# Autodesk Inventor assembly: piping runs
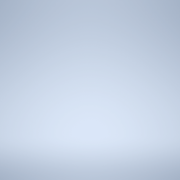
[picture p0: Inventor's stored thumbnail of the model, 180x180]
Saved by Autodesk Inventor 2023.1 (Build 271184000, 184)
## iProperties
Name: Hydraulic Hose - Male Taper Thread
ActiveState: False
PipeType: Flexible Hose
RoutePreview: Solid
Material: UnInitValue
Standard: UnInitValue
FittingMaterial: UnInitValue
FittingStandard: UnInitValue
RouteDirection90: UnInitValue
RouteDirection45: UnInitValue
DiameterType: Nominal
Diameter: 1/2
Schedule: ID=0.5
OD: 2.235200000000000e+000
ID: 1.270000000000000e+000
Ending: UnInitValue
IntermediateSegmentsMin: UnInitValue
IntermediateSegmentsMax: UnInitValue
IntermediateSegmentsInc: UnInitValue
TerminationSegmentsMin: UnInitValue
TerminationSegmentsMax: UnInitValue
TerminationSegmentsInc: UnInitValue
RoundUpValue: 0.125 in
SolidRoutePreviewColor: 12632064
PipingComponentColor: As Material
PipeKey: v3#d489867e-ac9b-47ea-b952-0a1b885f66be#4
CouplingKey: UnInitValue
Elbow90Key: UnInitValue
Elbow45Key: UnInitValue
_ComponentInfo: <CS><C N="Pipe" R="1.117600" OR="1.117600" IR="0.635000" PL="PL" PartType="" SymKey="" PN="Parker Hydraulic Hose - No Skive 1/2"><CO N="1"><FE V="0"/><FD V="0"/
BendRadius: 0.500 in
StartFittingKey: v3#c8250148-a7b6-458b-b7bd-3b56763ca7cc#13
EndFittingKey: v3#c8250148-a7b6-458b-b7bd-3b56763ca7cc#13
SuppressStartFitting: False
SuppressEndFitting: False
UseSubASM: True
DefaultBendRadius: UnInitValue
FlangeKey: UnInitValue
Gap: UnInitValue
GasketKey: UnInitValue
IsButtWelded: UnInitValue
IsFlanged: UnInitValue
MixedUnits: UnInitValue
ShowGap: UnInitValue
UseFlangsForCouplings: UnInitValue
BendRadius: UnInitValue
Diameter: 6
Elbow90Key: v3#97ecdcaf-8aa3-4fb0-8b6a-3da783de2ad5#108
EndFittingKey: UnInitValue
Gap: 0.062 inch
ID: UnInitValue
IntermediateSegmentsInc: 0.00001 in
IntermediateSegmentsMax: 200 inch
IntermediateSegmentsMin: 3 inch
IsButtWelded: True
IsFlanged: False
Name: ASTM A 53/A-ASME B16.9 - Steel Butt Welded Pipe
OD: UnInitValue
PipeKey: v3#4ce5e9fa-6da0-4801-ac02-ee7a0fb518d6#77
PipeType: Rigid Pipe
RoundUpValue: UnInitValue
RouteDirection45: False
RouteDirection90: True
Schedule: 40
ShowGap: True
StartFittingKey: UnInitValue
SuppressEndFitting: UnInitValue
SuppressStartFitting: UnInitValue
TerminationSegmentsInc: 0.00001 in
TerminationSegmentsMax: 200 inch
TerminationSegmentsMin: 3 inch
UseSubASM: UnInitValue
_ComponentInfo: <CS><C N="Elbow90" ER="15.240000" S1="15.240000" S2="15.240000" D1="0.000000" D2="0.000000" PartType="fitting" SymKey="ELBW"><CO N="1"><FE V="2"/><FD V="0"/><ET
MixedUnits: False
Name: JIS G 3458/JIS B 2316 -  Welded Steel Pipe and Fittings
RouteDirection45: True
Diameter: M40
Schedule: 80
IntermediateSegmentsMin: 60.000 mm
IntermediateSegmentsMax: 5000.000 mm
IntermediateSegmentsInc: 1.000 mm
TerminationSegmentsMin: 60.000 mm
TerminationSegmentsMax: 5000.000 mm
TerminationSegmentsInc: 1.000 mm
PipeKey: v3#da14b0ab-0b36-4851-8d66-8c9cd0bcbe86#23
CouplingKey: v3#12b64993-10e6-4915-8315-0c0cce209ad0#8
Elbow90Key: v3#1f65ece3-c41a-48d4-8661-909ed34ade86#8
Elbow45Key: v3#28e76e79-e22c-40ab-8be2-ff545b1407c5#8
_ComponentInfo: <CS><C N="Pipe" R="2.430000" IR="1.920000" PL="PL" PN="JIS G 3458 Pipe 40 A x Sch 80"><CO N="1"><FE V="0"/><FD V="1"/><ET V="Welded"/><NS  V="M40"/><MA V="0.000
CategoryName: UnInitValue
Name: Hydraulic Hose - Female Taper Thread
StartFittingKey: v3#cc3bd835-95a2-497d-9893-176cd9c426f6#7
EndFittingKey: v3#cc3bd835-95a2-497d-9893-176cd9c426f6#7
Name: Hydraulic Hose - SAE Flanged Connection
StartFittingKey: v3#933069c9-73b6-4141-af99-628d4a97b2c2#1
EndFittingKey: v3#933069c9-73b6-4141-af99-628d4a97b2c2#1
Name: ASTM A53/A53M-ASME B16.11 - Welded Steel Pipe
Material: Steel
Standard: ASTM A 53/A 53M
FittingMaterial: Steel
FittingStandard: ASME B16.11
OD: Undefined
ID: Undefined
IntermediateSegmentsMin: 1.000 in
IntermediateSegmentsMax: 200.000 in
IntermediateSegmentsInc: 0.100 in
TerminationSegmentsMin: 1.000 in
TerminationSegmentsMax: 200.000 in
TerminationSegmentsInc: 0.100 in
PipeKey: v3#4ce5e9fa-6da0-4801-ac02-ee7a0fb518d6#7
CouplingKey: v3#ed415c76-4cec-44a3-ba67-72e47bf70384#4
Elbow90Key: v3#82a08401-12d7-413b-b7f9-9cf3b607be7b#4
Elbow45Key: v3#2e5fd082-3851-4eb0-bde1-6c7078a7d72b#4
_ComponentInfo: <CS><C N="Pipe" R="1.066800" IR="0.789940" PL="PL" PN="ASTM A 53/A 53M Pipe 1/2 - Schedule 40"><CO N="1"><FE V="0"/><FD V="0"/><ET V="Welded"/><NS  V="1/2"/><MA
Elbow90Key: v3#6a678020-d9d9-4685-bba9-906b9a167083#10
FlangeKey: v3#c11442d2-c568-438f-a870-8ac9b5b636cb#10
GasketKey: v3#2a41914c-f5fb-4682-9c6a-1870d826d3d0#23
IntermediateSegmentsInc: 0.1 inch
IsButtWelded: False
IsFlanged: True
Name: ASTM A 53/A-ASME B16.5 - Flanged Steel Threaded Pipe
PipeKey: v3#c5bd7d28-cdb3-4507-9f3d-c2787d93fe8a#40
TerminationSegmentsInc: 0.1 inch
_ComponentInfo: <CS><C N="Elbow90" ER="21.590000" S1="21.590000" S2="21.590000" D1="0.000000" D2="0.000000" PartType="fitting" SymKey="ELFL"><CO N="1"><FE V="2"/><FD V="1"/><ET
ElbowCustomKey: UnInitValue
IsSelfDraining: False
Name: ISO 2531 - Flanged Ductile Iron Pipe and Fittings
Schedule: PN10
IntermediateSegmentsMin: 1000.000 mm
IntermediateSegmentsMax: 9000.000 mm
IntermediateSegmentsInc: 10.000 mm
TerminationSegmentsMin: 1000.000 mm
TerminationSegmentsMax: 9000.000 mm
TerminationSegmentsInc: 10.000 mm
PipeKey: v3#f52fbdcb-ece8-4303-8b76-5dbe8c7f2f9c#16
Elbow90Key: v3#451ae64e-c79d-4cba-b533-c09b8090ecb2#1
Elbow45Key: v3#81684a3f-f2a4-4fe6-95b1-f067ddead22f#1
_ComponentInfo: <CS><C N="Pipe" R="2.700000" IR="2.000000" PL="PL" PN="ISO 2531 Pipe with Integrally Cast Flanges DN40 PN 10"><CO N="1"><FE V="0"/><FD V="0"/><ET  V="Flanged"/>
Name: ASME B36.10M-ASME B16.11 - Steel Threaded Pipe
ActiveState: True
Material: Wrought Steel
Standard: ASME B36.10M
Schedule: 30
OD: 2.1336
ID: 1.651
IntermediateSegmentsMin: 2.000 in
TerminationSegmentsMin: 2.000 in
PipeKey: v3#4a736116-503a-44ad-a922-868ac6b46736#1
CouplingKey: v3#52ad3977-2b89-4007-a6a6-7626bac0ae85#4
Elbow90Key: v3#160eac10-3e6f-4b5c-839c-61eee0d373dc#4
Elbow45Key: v3#5c2ab816-abcb-49a6-a106-4733af000f51#4
_ComponentInfo: <CS><C N="Pipe" R="1.066800" IR="0.825500" PL="PL" PN="ASME B36.10M Pipe with Threaded Ends 1/2 - Schedule 30"><CO N="1"><FE V="0"/><FD V="1"/><ET  V="Threaded"
Angle: 92.00 deg
Diameter: 1
Elbow45Key: v3#bf26aa2a-f3dd-474c-8758-922a145c2b02#15
Elbow90Key: v3#3e93288f-9bb7-4e46-9d6b-544f8c20ca1c#3
ElbowCustomKey: v3#1f3bd44a-47ab-42f9-b3e0-74afa0c3f0ca#3
Gap: 0.094 in
IsSelfDraining: True
Name: ASME BPE - Butt Welded
PipeKey: v3#b10c956f-6fc6-429e-8056-0864a8581764#35
Schedule: ID=0.87
_ComponentInfo: <CS><C N="Pipe" R="1.270000" OR="1.270000" IR="1.104900" PL="PL" PartType="pipe" SymKey="" PN="ASTM A 269 Tube with Welded ends 1 x 0.87"><CO N="1"><FE V="2"/><
Name: DIN 2458/DIN 2605 - Welded Steel Pipe and Fittings
Schedule: ID=30.7
PipeKey: v3#dcef2839-8903-4c98-a96c-b861f5d9bb7f#98
Elbow90Key: v3#ace818b0-7b7c-4ad9-b19c-6da358a202c1#17
Elbow45Key: v3#97879d80-057e-491b-840b-74a9b3a7cf63#17
_ComponentInfo: <CS><C N="Pipe" R="2.415000" IR="1.535000" PL="PL" PN="DIN 2458 Pipe 48.3 x 8.8"><CO N="1"><FE V="2"/><FD V="0"/><ET V="Welded"/><NS V="M40"/><MA  V="0.000000"/
Name: JIS G 3442/JIS B 2301 Threaded Steel Pipe and Iron Fittings
Schedule: ID=16.1
IntermediateSegmentsMin: 20.000 mm
TerminationSegmentsMin: 20.000 mm
PipeKey: v3#9964fba4-9d5a-4d75-85a8-e38022ccdce1#2
CouplingKey: v3#181262db-c004-4877-bc40-c64b931a44f6#3
Elbow90Key: v3#6c92b367-65e9-486b-b952-db434ae2548d#3
Elbow45Key: v3#960407aa-00b9-4d72-aae7-d50595845cfd#3
_ComponentInfo: <CS><C N="Pipe" R="1.085000" IR="0.805000" PL="PL" PN="JIS G 3442 Pipe with Threaded Ends 21.7 x 2.8"><CO N="1"><FE V="0"/><FD V="1"/><ET V="Threaded"/><NS V="1
Name: Hydraulic Hose - Female Thread - Swivel
StartFittingKey: v3#c5e461f5-5e73-4f2e-8c1e-4358d4d6f46c#4
EndFittingKey: v3#c5e461f5-5e73-4f2e-8c1e-4358d4d6f46c#4
Created: 2006-09
Part Number: piping runs
Document SubType Name: Tube & Pipe
Designer: Autodesk
Manufacturer: Standard
Standards Organization: Custom
Name: ASTM B 88-ASME B16.22 - Soldered Copper Tubing
PipeType: Tubing
Material: Copper
Standard: ASTM B 88
FittingMaterial: *
FittingStandard: ASME B16.22
Schedule: L
IntermediateSegmentsMin: 0.000 in
IntermediateSegmentsMax: 100.000 in
TerminationSegmentsMin: 0.000 in
TerminationSegmentsMax: 100.000 in
SolidRoutePreviewColor: 49344
PipeKey: v3#44b182c9-4bce-4825-bb4d-596143122252#7
CouplingKey: v3#0dc1ae02-7bbf-4ccf-8498-581434b0a765#3
_ComponentInfo: <CS><C N="Pipe" R="0.793750" IR="0.692150" PL="PL" PN="ASTM B 88 Tube 1/2 - Type L"><CO N="1"><FE V="0"/><FD V="0"/><ET V="Soldered"/><NS V="1/2"/><MA V="2.5400
DefaultBendRadius: 2.000 in
FlangeKey: v3#24991861-26e3-4c21-a713-f46e314eddd5#10
IntermediateSegmentsMin: 3.000 in
Name: ASTM A 53/A 53M - Butt Welded/Flanged Steel Pipe
TerminationSegmentsMin: 3.000 in
UseFlangsForCouplings: False
_ComponentInfo: <CS><C N="Pipe" R="8.413750" OR="8.413750" IR="7.702550" PL="PL" PartType="pipe" SymKey="" PN="ASTM A 53/A 53M Pipe 6 - Schedule 40"><CO N="1"><FE V="2"/><FD V=
Name: ISO 7598/ISO 49 - Threaded Steel Pipe with Iron Fittings
IntermediateSegmentsMin: 50.800 mm
IntermediateSegmentsMax: 5080.000 mm
IntermediateSegmentsInc: 2.540 mm
TerminationSegmentsMin: 50.800 mm
TerminationSegmentsMax: 5080.000 mm
TerminationSegmentsInc: 2.540 mm
PipeKey: v3#1052637f-74b5-47f4-adeb-d4e8d3fa53b8#1
CouplingKey: v3#7e56b2cb-a132-4546-b8a7-a14538454b94#3
Elbow90Key: v3#b72bb08b-ad33-47cc-a03d-7f3d76c6616b#3
Elbow45Key: v3#a96c5204-26e4-4bb2-b8f1-f0623fbc94bb#2
_ComponentInfo: <CS><C N="Pipe" R="1.065000" IR="0.805000" PL="PL" PN="ISO 7598 Tube with Threaded Ends DN15"><CO N="1"><FE V="0"/><FD V="1"/><ET V="Threaded"/><NS V="1/2"/><MA
Name: ASTM D 1785-ASTM D 2466 - Jointed PVC Pipe and Fittings
Material: PVC-Piping
Standard: ASTM D 1785
FittingMaterial: PVC-Piping
FittingStandard: ASTM D 2466
PipeKey: v3#4bf12049-4375-491b-8f13-d4ee0c517c57#1
CouplingKey: v3#29993622-4c6a-437e-8b8c-43a0846f8735#1
Elbow90Key: v3#25d2a8db-6517-4627-a5a4-9d27e4d26b9b#1
Elbow45Key: v3#d7b5d569-4a12-4d65-ba55-12203d6ac7ed#1
_ComponentInfo: <CS><C N="Pipe" R="1.066800" IR="0.789940" PL="PL" PN="ASTM D 1785 Pipe 1/2 - Schedule 40"><CO N="1"><FE V="0"/><FD V="0"/><ET V="Jointed"/><NS  V="1/2"/><MA V=
Name: DIN 8062/DIN 8063 - Jointed PVC-U Pipe and Fittings
Schedule: 6.3
PipeKey: v3#3d294dc7-89c3-4c37-a0ae-28c15a73bfd0#13
CouplingKey: v3#3edf83e2-464b-4b31-84c5-c329ffbf2a4f#5
Elbow90Key: v3#fbd68fd5-590c-4cb5-8c20-9e9bdd396a04#5
Elbow45Key: v3#2f597a97-b15b-49d4-87cb-7bfe69eb62ee#5
_ComponentInfo: <CS><C N="Pipe" R="2.000000" IR="1.700000" PL="PL" PN="DIN 8062 Pipe 40 x 3"><CO N="1"><FE V="0"/><FD V="0"/><ET V="Jointed"/><NS V="M40"/><MA  V="8.000000"/><M
Name: JIS K 6741/JIS K 6739 - Jointed PVC-U Pipe and Fittings
Schedule: VP
IntermediateSegmentsMax: 2500.000 mm
TerminationSegmentsMax: 2500.000 mm
PipeKey: v3#45338dd0-af69-48c0-a2ed-8ade33a08701#5
CouplingKey: v3#eaa8de87-dc67-4eca-ba7e-4267a30f8f7f#2
Elbow90Key: v3#c4513a61-3106-4a78-baf9-a1badd100245#2
Elbow45Key: v3#2769403e-a4fd-4a4c-8e4c-659ea845bd78#2
_ComponentInfo: <CS><C N="Pipe" R="2.400000" IR="2.040000" PL="PL" PN="JIS K 6741 Pipe VP 40"><CO N="1"><FE V="0"/><FD V="1"/><ET V="Jointed"/><NS V="M40"/><MA  V="4.000000"/><
Name: DIN 2458/DIN EN 10242 - Threaded Steel Pipe and Iron Fittings
Schedule: ID=12.3
PipeKey: v3#d689fd5f-ac5a-46d7-a883-3089b2f6e0a4#28
CouplingKey: v3#d2599e7a-1865-48da-a234-5418a1cd5dfe#3
Elbow90Key: v3#9fba244e-81ed-4fc6-a9ac-7eb372fa3ffe#3
Elbow45Key: v3#6ce5b1be-37aa-4928-b23a-0df64e6ddf38#2
_ComponentInfo: <CS><C N="Pipe" R="1.065000" IR="0.615000" PL="PL" PN="DIN 2458 Pipe with Threaded Ends 21.3 x 4.5"><CO N="1"><FE V="0"/><FD V="1"/><ET V="Threaded"/><NS V="1/2
Name: ANSI/ASME B36.19M-ASME B16.3 - Threaded Pipe with Iron Fittings
Material: Stainless Steel
Standard: ANSI/ASME B36.19M
FittingMaterial: Malleable Iron
FittingStandard: ASME B16.3
Schedule: 40S
PipeKey: v3#323c0148-c750-449d-a0c6-11721f2a5046#1
CouplingKey: v3#771d4942-b9e7-43bc-9d41-ab12a9580492#3
Elbow90Key: v3#bc6b44ab-9235-4590-b699-74498030a1ff#3
Elbow45Key: v3#626cc28c-1a24-4045-be0d-40d896dc828d#3
_ComponentInfo: <CS><C N="Pipe" R="1.066800" IR="0.789940" PL="PL" PN="ANSI/ASME B36.19M Pipe with Threaded Ends 1/2 - Schedule 40S"><CO N="1"><FE V="0"/><FD  V="1"/><ET V="Thr
count: 29
Refkey_Axis1_Context: 2|0|0|0|1|0|0|0|
Refkey_Axis1: 6|0|0|0|44|0|0|0|78|0|65|0|77|0|69|0|83|0|10|0|67|0|111|0|108|0|111|0|114|0|115|0|10|0|49|0|58|0|10|0|10|0|69|0|78|0|68|0|10|0|0|0|
Refkey_Axis2_Context: 2|0|0|0|1|0|0|0|
Refkey_Axis2: 6|0|0|0|88|0|0|0|78|0|65|0|77|0|69|0|83|0|10|0|67|0|111|0|108|0|111|0|114|0|115|0|10|0|49|0|58|0|82|0|111|0|117|0|116|0|101|0|32|0|85|0|73|0|32|0|84|0|111|0|111
Refkey_Axis3_Context: 2|0|0|0|1|0|0|0|
Refkey_Axis3: 6|0|0|0|88|0|0|0|78|0|65|0|77|0|69|0|83|0|10|0|67|0|111|0|108|0|111|0|114|0|115|0|10|0|49|0|58|0|82|0|111|0|117|0|116|0|101|0|32|0|85|0|73|0|32|0|84|0|111|0|111
Refkey_Ext_Context: 2|0|0|0|1|0|0|0|
Refkey_Ext: 6|0|0|0|92|0|0|0|78|0|65|0|77|0|69|0|83|0|10|0|67|0|111|0|108|0|111|0|114|0|115|0|10|0|49|0|58|0|82|0|111|0|117|0|116|0|101|0|32|0|85|0|73|0|32|0|84|0|111|0|111
Refkey_Snap_Context: 2|0|0|0|1|0|0|0|
Refkey_Snap: 6|0|0|0|84|0|0|0|78|0|65|0|77|0|69|0|83|0|10|0|67|0|111|0|108|0|111|0|114|0|115|0|10|0|49|0|58|0|82|0|111|0|117|0|116|0|101|0|32|0|85|0|73|0|32|0|84|0|111|0|111
Name: Hydraulic Hose - Male Straight Thread
StartFittingKey: v3#b50cb43e-68c0-48ac-8e25-7ef224ce0e6c#3
EndFittingKey: v3#b50cb43e-68c0-48ac-8e25-7ef224ce0e6c#3
Name: ISO 4065-ISO 3633 - PVC Pipe and Fittings
Schedule: S40
IntermediateSegmentsMax: 2540.000 mm
TerminationSegmentsMax: 2540.000 mm
PipeKey: v3#4f84f716-5ba0-45ef-967a-c32c3d7345ce#70
CouplingKey: v3#b06656e5-2b55-488c-bcf0-6a90c79c4683#2
Elbow90Key: v3#17490b17-1dd8-40fc-8de7-1a70c3bab2d7#1
Elbow45Key: v3#421a8b99-1721-409a-bc3b-c00889561754#1
_ComponentInfo: <CS><C N="Pipe" R="2.000000" IR="1.950000" PL="PL" PN="ISO 4065 Pipe 40 x 0.5 S40"><CO N="1"><FE V="0"/><FD V="0"/><ET V="Jointed"/><NS V="M40"/><MA  V="6.00000
Name: Hydraulic Hose - No Fittings
SuppressStartFitting: True
SuppressEndFitting: True
Author: Autodesk
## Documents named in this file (1)
- M:\AUTOBUILD\INV.Official.R1\Application\App\Design Data\Tube & Pipe\piping runs.iam
